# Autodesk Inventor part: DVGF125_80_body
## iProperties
Created: 2010-04
Part Number: DVGF125_80_body
Document SubType Name: Modeling
Designer: TB
Mass: 3150.34 g
Surface Area: 3366.2 cm^2
Volume: 3150.34 cm^3
Density: 1 g/cm^3
Author: TB
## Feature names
1. Kropp [Revolution]
2. Chamfer
3. Extrusion2
4. Hole1
5. Revolution2
6. Hole2
7. Fillet1
8. Extrusion3
9. Hole3
